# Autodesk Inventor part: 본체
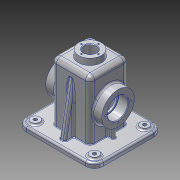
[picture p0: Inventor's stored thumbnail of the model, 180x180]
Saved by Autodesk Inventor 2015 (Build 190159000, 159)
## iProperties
Created: 2016-02
Part Number: 본체
Material: 알루미늄 6061
Document SubType Name: Modeling
Designer: Administrator
Density: 2.7 g/cm^3
Appearance: 알루미늄 - 평지
Mass: 800.036 g
Surface Area: 908.079 cm^2
Volume: 296.31 cm^3
Author: Administrator
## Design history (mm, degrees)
sketch "스케치1"
  geometry: L1 (-65, -57.5)-(65, -57.5); L2 (65, -57.5)-(65, 57.5); L3 (65, 57.5)-(-65, 57.5); L4 (-65, 57.5)-(-65, -57.5); L5 (-65, -57.5)-(65, 57.5); L6 (65, -57.5)-(-65, 57.5); 1 further point
  constraints: 12 end point, 2 midpoint, 2 parallel, 1 horizontal, 1 perpendicular
  dimensions: "d0" = 130 distance of L3.end L2.end; "d1" = 115 distance of L2.end L1.end
extrude "돌출1" new body sketch "스케치1" distance "d2" = 8; taper "d3" = 0 deg
fillet "모깎기1" dims "d4" = 15
sketch "스케치2"
  geometry: L1 (-50, -57.5)-(50, -57.5) reference; L2 (-50, -57.5)-(50, -57.5) reference; L3 (65, -42.5)-(65, 42.5) reference; L4 (50, 57.5)-(-50, 57.5) reference; L5 (-65, 42.5)-(-65, -42.5) reference; C1 r 7.5 at (50, -42.5); C2 r 7.5 at (-50, -42.5); C3 r 7.5 at (50, 42.5); C4 r 7.5 at (-50, 42.5); A1 r 15 centre (-50, -42.5) between (-65, -42.5) and (-50, -57.5) reference; A2 r 15 centre (50, -42.5) between (50, -57.5) and (65, -42.5) reference; A3 r 15 centre (50, 42.5) between (65, 42.5) and (50, 57.5) reference; A4 r 15 centre (-50, 42.5) between (-50, 57.5) and (-65, 42.5) reference; 1 further point
  constraints: 4 centre point, 1 horizontal, 1 vertical, 6 other
  dimensions: "d5" = 15 diameter of C1; "d6" = 50 horizontal distance of point (0, 0) C1.centre; "d7" = 42.5 vertical distance of point (0, 0) C1.centre; "d10" = 100 distance of C1.centre C2.centre; "d13" = 85 distance of C1.centre C3.centre
extrude "돌출2" join sketch "스케치2" distance "d16" = 3; taper "d17" = 0 deg
sketch "스케치3"
  geometry: L1 (-60, -52.5)-(60, -52.5); L2 (60, -52.5)-(60, 52.5); L3 (60, 52.5)-(-60, 52.5); L4 (-60, 52.5)-(-60, -52.5); L5 (-60, -52.5)-(60, 52.5); L6 (60, -52.5)-(-60, 52.5); 1 further point
  constraints: 12 end point, 2 midpoint, 2 parallel, 1 horizontal, 1 perpendicular
  dimensions: "d54" = 120 distance of L3.end L2.end; "d55" = 105 distance of L2.end L1.end
extrude "돌출3" join sketch "스케치3" distance "d56" = 2; taper "d57" = 0 deg
fillet "모깎기2" dims "d58" = 10
sketch "스케치4"
  geometry: L1 (5, 47.5)-(-5, 47.5); L2 (-5, 47.5)-(-5, -47.5); L3 (-5, -47.5)-(5, -47.5); L4 (5, -47.5)-(5, 47.5); L5 (5, 47.5)-(-5, -47.5); L6 (-5, 47.5)-(5, -47.5); 1 further point
  constraints: 12 end point, 2 midpoint, 2 parallel, 1 horizontal, 1 perpendicular
  dimensions: "d59" = 10 distance of L3.end L2.end; "d60" = 95 distance of L2.end L1.end
extrude "돌출4" join sketch "스케치4" distance "d61" = 100; taper "d62" = 0 deg
feature "면 기울기1" dims angle "d63" = 10 deg
feature "면 기울기2" dims angle "d64" = 10 deg
sketch "스케치5"
  geometry: L1 (-32.5, 32.5)-(32.5, 32.5); L2 (32.5, 32.5)-(32.5, -32.5); L3 (32.5, -32.5)-(-32.5, -32.5); L4 (-32.5, -32.5)-(-32.5, 32.5); L5 (-32.5, 32.5)-(32.5, -32.5); L6 (32.5, 32.5)-(-32.5, -32.5); 1 further point
  constraints: 12 end point, 2 midpoint, 2 parallel, 1 horizontal, 1 perpendicular
  dimensions: "d65" = 65 distance of L2.end L3.end; "d66" = 65 distance of L1.end L2.end
extrude "돌출5" join sketch "스케치5" distance "d67" = 100; taper "d68" = 0 deg
sketch "스케치6"
  geometry: C1 r 10.5 at (0, 0); 1 further point
  constraints: 1 centre point, 1 coincident
  dimensions: "d69" = 21 diameter of C1
extrude "돌출6" cut sketch "스케치6" stored distance "d70" = 110; taper "d71" = 0 deg
sketch "스케치7"
  geometry: L1 (-27.5, 27.5)-(27.5, 27.5); L2 (27.5, 27.5)-(27.5, -27.5); L3 (27.5, -27.5)-(-27.5, -27.5); L4 (-27.5, -27.5)-(-27.5, 27.5); L5 (-27.5, 27.5)-(27.5, -27.5); L6 (27.5, 27.5)-(-27.5, -27.5); 1 further point
  constraints: 12 end point, 2 midpoint, 2 parallel, 1 horizontal, 1 perpendicular
  dimensions: "d72" = 55 distance of L2.end L3.end; "d73" = 55 distance of L1.end L2.end
extrude "돌출7" cut sketch "스케치7" distance "d74" = 105; taper "d75" = 0 deg
sketch "스케치8"
  geometry: C1 r 20 at (0, 0); 1 further point
  constraints: 1 centre point, 1 coincident
  dimensions: "d76" = 40 diameter of C1
extrude "돌출8" join sketch "스케치8" distance "d77" = 10; taper "d78" = 0 deg
hole "구멍5" diameter "d81" = 21; stored, may be unused: countersink angle "d85" = 90 deg, drill point angle "d87" = 118 deg; dims "d79" = 10, "d80" = 10, "d82" = 7, "d83" = 4, "d84" = 2, "d86" = 21
sketch "스케치9" dims "d88" = 29
  geometry: 6 further points
  constraints: 2 vertical alignment, 1 coincident, 7 other
  dimensions: "d91" = 360 deg dimension on point (0, 0) point (0, 14.5) (derived)
hole "구멍6" sketch "스케치9" at (0, 14.5), (-14.5, 0), (0, -14.5), (14.5, 0) diameter "d93" = 2.459; stored, may be unused: countersink angle "d97" = 90 deg, drill point angle "d99" = 118 deg; dims "d94" = 7, "d95" = 4, "d96" = 2, "d98" = 9
feature "면 기울기3" dims angle "d100" = 5 deg
sketch "스케치10"
  geometry: L1 (42.5, 3)-(-42.5, 3); L2 (-42.5, 3)-(-42.5, -3); L3 (-42.5, -3)-(42.5, -3); L4 (42.5, -3)-(42.5, 3); L5 (42.5, 3)-(-42.5, -3); L6 (-42.5, 3)-(42.5, -3); 1 further point
  constraints: 12 end point, 2 midpoint, 2 parallel, 1 horizontal, 1 perpendicular
  dimensions: "d101" = 85 distance of L3.end L2.end; "d102" = 6 distance of L2.end L1.end
extrude "돌출9" join sketch "스케치10" distance "d103" = 30; taper "d104" = 0 deg
sketch "스케치11"
  geometry: L1 (108, -10)-(108, 75) reference; C1 r 27.5 at (53, 32.5); 2 further points
  constraints: 1 centre point, 1 horizontal alignment, 1 midpoint
  dimensions: "d105" = 55 diameter of C1; "d106" = 55 distance from line of L1 C1.centre
extrude "돌출10" join sketch "스케치11" distance "d107" = 15; taper "d108" = 0 deg
hole "구멍7" diameter "d111" = 30; stored, may be unused: countersink angle "d115" = 90 deg, drill point angle "d117" = 0 deg; dims "d109" = 10, "d110" = 10, "d112" = 7, "d113" = 4, "d114" = 2, "d116" = 30
hole "구멍8" diameter "d120" = 35; stored, may be unused: countersink angle "d124" = 90 deg, drill point angle "d126" = 0 deg; dims "d118" = 10, "d119" = 10, "d121" = 7, "d122" = 4, "d123" = 2, "d125" = 17
sketch "스케치12" dims "d127" = 42
  geometry: L1 (44, -35.429)-(47, -35.429) reference; L2 (47, -35.429)-(47, 35.429) reference; L3 (47, 35.429)-(44, 35.429) reference; L4 (44, 35.429)-(44, 49.571) reference; L5 (44, 49.571)-(47, 49.571) reference; L6 (47, 49.571)-(47, 57.5) reference; L7 (47, 57.5)-(55, 57.5) reference; L8 (55, 57.5)-(55, 52.5) reference; L9 (55, -52.5)-(55, -57.5) reference; L10 (55, -57.5)-(47, -57.5) reference; L11 (47, -57.5)-(47, -49.571) reference; L12 (47, -49.571)-(44, -49.571) reference; L13 (44, -49.571)-(44, -35.429) reference; L14 (55, 52.5)-(57, 52.5) reference; L15 (57, 52.5)-(57, -52.5) reference; L16 (57, -52.5)-(55, -52.5) reference; C1 r 17.5 at (0, 0) reference; C2 r 27.5 at (0, 0) reference; 6 further points
  constraints: 2 horizontal alignment, 1 coincident, 7 other
  dimensions: "d130" = 360 deg dimension on point (0, 0) point (-21, 0) (derived)
hole "구멍9" sketch "스케치12" at (-21, 0), (0, -21), (21, 0), (0, 21) diameter "d132" = 3.242; stored, may be unused: countersink angle "d136" = 90 deg, drill point angle "d138" = 118 deg; dims "d133" = 8, "d134" = 4, "d135" = 2, "d137" = 10
chamfer "모따기1" distance "d139" = 1; stored, may be unused: second distance "d140" = 2, angle "d141" = 45 deg
fillet "모깎기3" dims "d142" = 0.3
sketch "스케치13"
  geometry: L1 (27.5, 27.5)-(-27.5, 27.5); L2 (-27.5, 27.5)-(-27.5, -27.5); L3 (-27.5, -27.5)-(27.5, -27.5); L4 (27.5, -27.5)-(27.5, 27.5); L5 (27.5, 27.5)-(-27.5, -27.5); L6 (-27.5, 27.5)-(27.5, -27.5); 1 further point
  constraints: 12 end point, 2 midpoint, 2 parallel, 1 horizontal, 1 perpendicular
extrude "돌출11" cut sketch "스케치13" distance "d143" = 50; taper "d144" = 0 deg
fillet "모깎기4" dims "d145" = 3
fillet "모깎기5" dims "d146" = 3
fillet "모깎기6" dims "d147" = 3
fillet "모깎기7" dims "d148" = 3
fillet "모깎기9" dims "d150" = 3
fillet "모깎기11" dims "d152" = 8
fillet "모깎기12" dims "d153" = 8
fillet "모깎기14" dims "d155" = 3
fillet "모깎기15" dims "d156" = 3
sketch "스케치14"
  geometry: L1 (18, 5.375)-(18, 43.625) reference; L2 (0, 57)-(-92, 57) reference; 3 further points
  constraints: 1 other
  dimensions: "d157" = 26 distance from line of point (-8, 24.5) L1; "d158" = 32.5 distance from line of point (-8, 24.5) L2
feature "엠보싱1" sketch "스케치14" dims "d159" = 0.5, "d160" = 0
chamfer "모따기2" distance "d161" = 1; stored, may be unused: second distance "d162" = 2, angle "d163" = 45 deg
hole "구멍10" diameter "d166" = 6; stored, may be unused: countersink angle "d170" = 90 deg, drill point angle "d172" = 0 deg; dims "d164" = 10, "d165" = 10, "d167" = 8, "d168" = 4, "d169" = 2, "d171" = 6
fillet "모깎기16" dims "d173" = 3
fillet "모깎기17" dims "d174" = 1
node "솔리드1"
mirror "대칭1"
mirror "대칭2"
mirror "대칭3"
node "투영된 루프1"
node "절단 모서리 투영1"
